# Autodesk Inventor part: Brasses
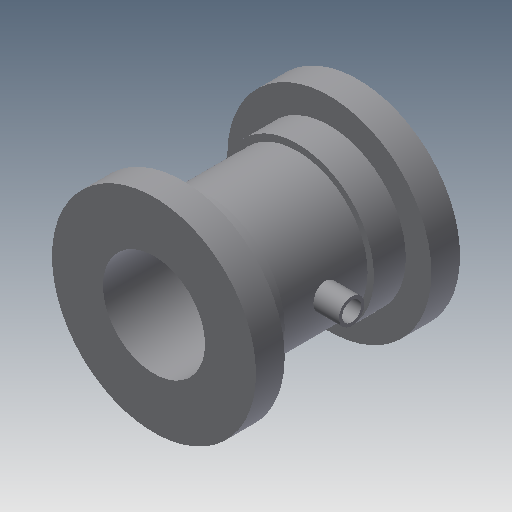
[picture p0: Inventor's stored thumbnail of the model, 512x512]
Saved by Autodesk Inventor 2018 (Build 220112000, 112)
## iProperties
Created: 2009-04
Part Number: Brasses
Document SubType Name: Modeling
Designer: Sham
Density: 1 g/cm^3
Material: Generic
Appearance: Default
Author: Sham
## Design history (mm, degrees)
sketch "Sketch1"
  geometry: L1 (0, 32)-(9, 32); L2 (0, 16)-(64, 16); L3 (64, 32)-(55, 32); L4 (55, 32)-(55, 24); L5 (55, 24)-(47, 24); L6 (19, 22)-(47, 22); L7 (47, 24)-(47, 22); L8 (19, 22)-(19, 24); L9 (19, 24)-(9, 24); L10 (9, 24)-(9, 32); L11 (0, 32)-(0, 16); L12 (64, 32)-(64, 16); L13 (-12.8, 0)-(76.8, 0) reference; 1 further point
  constraints: 24 end point, 7 parallel, 4 perpendicular, 1 collinear, 1 horizontal, 1 vertical alignment, 1 other
  dimensions: "d0" = 9 distance of L1.start L1.end; "d2" = 16 distance from line of L2 point (0, 0); "d3" = 64 distance of L2.start L2.end; "d4" = 24 distance from line of point (0, 0) L5; "d5" = 28 distance of L6.start L6.end; "d6" = 22 distance from line of point (0, 0) L6; "d7" = 8 distance of L4.end L5.end
revolve "Revolution1" sketch "Sketch1" stored, may be unused: angle "d8" = 90 deg
workplane "Work Plane1"
sketch "Sketch2"
  geometry: C1 r 4 at (-32, 0)
  constraints: 1 centre point
  dimensions: "d10" = 8 diameter of C1
extrude "Extrusion1" join sketch "Sketch2" stored distance "d11" = 10; taper "d12" = 0 deg
sketch "Sketch3"
  geometry: C1 r 4 at (0, 0) reference; C2 r 3 at (0, 0)
  constraints: 1 centre point, 1 coincident
  dimensions: "d13" = 6 diameter of C2
extrude "Extrusion2" cut sketch "Sketch3" extent not by distance; stored distance "d14" = 10; taper "d15" = 0 deg
body "Solid1"
